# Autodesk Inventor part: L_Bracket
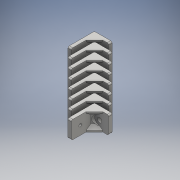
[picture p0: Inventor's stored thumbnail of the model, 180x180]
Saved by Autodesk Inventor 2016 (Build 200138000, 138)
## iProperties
Created: 2016-03
Part Number: L_Bracket
Material: Generic
Document SubType Name: Modeling
Designer: John
Density: 1 g/cm^3
Appearance: Default
Author: John
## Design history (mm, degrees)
sketch "Sketch1"
  geometry: L1 (0, -38.1)-(0, 0); L2 (0, 0)-(25.4, 0); L3 (25.4, 0)-(25.4, -5); L4 (25.4, -5)-(5, -5); L5 (5, -5)-(5, -38.1); L6 (5, -38.1)-(0, -38.1); 1 further point
  constraints: 12 end point, 6 perpendicular, 1 coincident, 1 vertical
  dimensions: "d0" = 38.1 distance of L1.start L1.end; "d1" = 25.4 distance of L1.end L2.end; "d2" = 5 distance between parallel lines of L2 L4
extrude "Extrusion1" new body sketch "Sketch1" distance "d3" = 25.4; taper "d4" = 0 deg
sketch "Sketch2"
  geometry: L1 (0, 0)-(25.4, 0) reference; L2 (0, 0)-(0, -25.4) reference; L3 (25.4, -25.4)-(0, -25.4) reference; L4 (25.4, 0)-(25.4, -25.4) reference; C1 r 3.25 at (12.7, -12.7); 3 further points
  constraints: 2 midpoint, 1 centre point, 1 horizontal alignment, 1 vertical alignment
  dimensions: "d5" = 6.5 diameter of C1
extrude "Extrusion2" cut sketch "Sketch2" stored distance "d6" = 25.4; taper "d7" = 0 deg
sketch "Sketch3"
  geometry: L1 (0, 33.1)-(0, 0) reference; L2 (0, 33.1)-(-25.4, 33.1) reference; L3 (-25.4, 0)-(-25.4, 33.1) reference; L4 (0, 0)-(-25.4, 0) reference; C1 r 3.25 at (-12.7, 12.7); 2 further points
  constraints: 1 centre point, 1 midpoint, 1 vertical alignment
  dimensions: "d8" = 12.7 distance from line of L4 C1.centre; "d9" = 6.5 diameter of C1
extrude "Extrusion3" cut sketch "Sketch3" stored distance "d10" = 25.4; taper "d11" = 0 deg
fillet "Fillet1" dims "d12" = 2
chamfer "Chamfer1" distance "d13" = 5; stored, may be unused: second distance "d14" = 2, angle "d15" = 45 deg
sketch "Sketch4"
  geometry: L1 (-15.4, 12.509)-(-15.4, 23.4) reference; L2 (-15.4, -2)-(-15.4, 8.891) reference; L3 (-2, -2)-(-15.4, -2) reference; L4 (0, 0)-(0, 21.4) reference; L5 (-15.4, 23.4)-(-2, 23.4) reference; C1 r 7.25 at (-12.7, 10.7); A1 r 3.25 centre (-12.7, 10.7) between (-15.4, 8.891) and (-15.4, 12.509) reference; A2 r 2 centre (-2, 0) between (-2, -2) and (0, 0) reference; A3 r 2 centre (-2, 21.4) between (0, 21.4) and (-2, 23.4) reference; 1 further point
  constraints: 1 centre point, 1 coincident
  dimensions: "d16" = 14.5 diameter of C1
extrude "Extrusion4" cut sketch "Sketch4" stored distance "d17" = 25.4; taper "d18" = 0 deg
sketch "Sketch5"
  geometry: L1 (23.4, 0)-(23.4, -5) reference; L2 (23.4, 0)-(0, 0) reference; L3 (0, 0)-(0, -36.1) reference; L4 (5, -36.1)-(0, -36.1) reference; L5 (5, -36.1)-(5, -10) reference; L6 (10, -5)-(5, -10) reference; L7 (10, -5)-(23.4, -5) reference; L8 (17.071, -5)-(5, -17.071); 1 further point
  constraints: 2 end point, 2 point on line, 1 parallel
  dimensions: "d21" = 5 distance between parallel lines of L6 L8
extrude "Extrusion5" join sketch "Sketch5" distance "d19" = 2; taper "d20" = 0 deg
chamfer "Chamfer2" distance "d22" = 5; stored, may be unused: second distance "d23" = 2, angle "d24" = 45 deg
workplane "Work Plane1"
mirror "Mirror1"
fillet "Fillet2" dims "d25" = 2
sketch "Sketch6"
  geometry: L1 (0, -2)-(0, -36.1) reference; L2 (5, -36.1)-(0, -36.1) reference; L3 (5, -36.1)-(5, -17.071) reference; L4 (5, -17.071)-(17.071, -5) reference; L5 (17.071, -5)-(23.4, -5) reference; L6 (23.4, 0)-(23.4, -5) reference; L7 (23.4, 0)-(2, 0) reference; L8 (2, -2)-(11.036, -11.036); A1 r 2 centre (2, -2) between (2, 0) and (0, -2) reference; 1 further point
  constraints: 2 end point, 1 midpoint
pattern_linear "Rectangular Pattern1" sketch "Sketch6" dims "d28" = 18
thicken "Thicken1" dims "d29" = 1.25, "d30" = 1.25
thicken "Thicken2" dims "d31" = 1.25, "d32" = 1.25
thicken "Thicken3" dims "d33" = 1.25, "d34" = 1.25
thicken "Thicken4" dims "d35" = 1.25, "d36" = 1.25
body "Solid1"
node "Projected Loop1"
node "Projected Loop2"
node "Projected Loop3"
node "Projected Loop4"
node "Projected Loop5"
